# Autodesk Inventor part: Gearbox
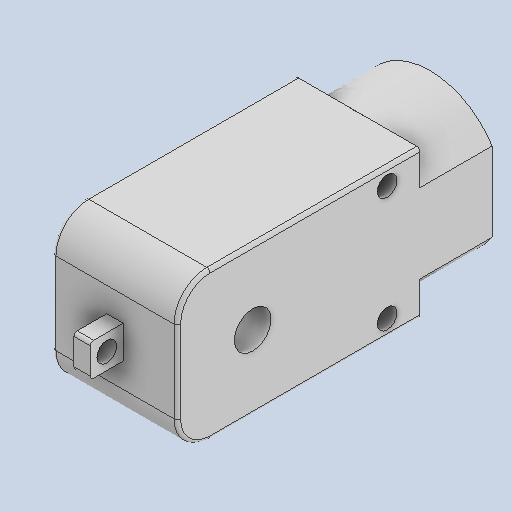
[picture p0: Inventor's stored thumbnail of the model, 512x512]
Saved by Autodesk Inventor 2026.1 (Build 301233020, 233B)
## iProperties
Created: 2019-04
Part Number: Gearbox
Material: Generic
Document SubType Name: Modeling
Designer: hp
Density: 1 g/cm^3
Appearance: Default
Author: hp
Revision Number: ANY
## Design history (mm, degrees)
feature "Cut-Extrude5"
body "Solid1"
